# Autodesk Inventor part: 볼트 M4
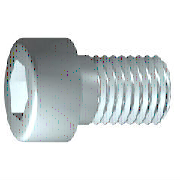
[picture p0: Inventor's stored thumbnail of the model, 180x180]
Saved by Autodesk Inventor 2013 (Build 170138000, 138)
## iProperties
IsCustomPart: 0
Created: 2014-10
Part Number: 볼트 M4
Material: 강철, 연강
Description: 6각머리 태핑 나사
Document SubType Name: Modeling
Standard: KS B 1003
Designer: KYOUNG IL JANG
Standards Organization: KS
Language: ko-KR
Size Designation: M 4 x 10
Categories: <MemberInstance><Categories><Category DisplayName="조임쇠" InternalName="e4da775c-781d-43d5-af7c-5136215cf5a6" Mnemonic="FSTN"><Category DisplayName="볼트" InternalN
Density: 7.86 g/cm^3
Mass: 2.0371 g
Surface Area: 3.0572 cm^2
Volume: 0.259174 cm^3
Author: SeoGD™ [www.esajin.kr]
Revision Number: 1
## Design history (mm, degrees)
sketch "스케치1"
  geometry: L1 (-1, 0)-(10, 0); L2 (10, 0)-(10, 2); L3 (10, 2)-(1.75, 2); L4 (1.75, 2)-(1.32, 2); L5 (1.32, 2)-(0, 2); L6 (0, 2)-(0, 3.5); L7 (0, 3.5)-(-4, 3.5); L8 (-4, 3.5)-(-4, 1.732); L9 (-4, 1.732)-(-2, 1.732); L10 (-2, 1.732)-(-1, 0); L11 (-6.8, 0)-(12.8, 0) reference; L12 (0, -0.7)-(0, 4.2) reference; L13 (1.75, 2)-(0, 2)
  constraints: 22 end point, 6 parallel, 2 collinear, 2 perpendicular, 1 horizontal, 1 point on line
  dimensions: "d1" = 8.25 distance from line of L3.end L2 (= GEL); "d2" = 0.42952 distance of L4.end L3.end (computed from GAL); "d3" = 4 distance between parallel lines of L8 L6 (= KOH); "d4" = 2 distance of L8.end L9.end (= INTI); "d5" = 60 deg angle of L10 L1; "d6" = 4 diameter of L3 L1 (= GD); "d7" = 4 diameter of L5 L1 (= BDM); "d8" = 3.4641 diameter of L9 L1 (= 1.1547 x SW); "d9" = 7 diameter of L7 L1 (= KOD); "d26" = 10 distance between parallel lines of L12 L2 (= NLG)
revolve "본체" sketch "스케치1" stored, may be unused: angle "d10" = 90 deg
sketch "스케치2"
  geometry: L1 (0, -4.9)-(0, 4.9) reference; L2 (-4.9, 0)-(4.9, 0) reference; L3 (1.732, 0)-(0.866, -1.5); L4 (0.866, -1.5)-(-0.866, -1.5); L5 (-0.866, -1.5)-(-1.732, 0); L6 (-1.732, 0)-(-0.866, 1.5); L7 (-0.866, 1.5)-(0.866, 1.5); L8 (0.866, 1.5)-(1.732, 0); 2 further points
  constraints: 12 end point, 1 coincident, 1 horizontal alignment, 1 point on line, 12 other
extrude "슬롯" join sketch "스케치2" stored distance "d11" = 10; taper "d12" = 0 deg
workplane "Work Plane1"
fillet "Fillet2" dims "d30" = 0.1 (= R)
body "Solid1"
fillet "모깎기1" dims "d17" = 0.4 (= RR)
feature "스레드" dims "d13" = 8.25 (= GEL), "d14" = 0
chamfer "모따기1" distance "d15" = 0.42941 (= -0.5 x SPD + 0.5 x GD); stored, may be unused: second distance "d16" = 0.42941 (= GUL), angle "d27" = 45 deg
other parameters: "GD" = 4 (= NND) [user parameter; used in 2 equation terms], "NLG" = 10 [user parameter; used in 1 equation term], "GEL" = 8.25 [user parameter; used in 2 equation terms], "KOD" = 7 [user parameter; used in 1 equation term], "KOH" = 4 [user parameter; used in 1 equation term], "INTI" = 2 [user parameter; used in 1 equation term], "GAL" = 0.42941 (= 0.61345 x PTC) [user parameter; used in 1 equation term], "GUL" = 0.42941 (= 0.61345 x PTC) [user parameter; used in 1 equation term], "BDM" = 4 (= NND) [user parameter; used in 1 equation term], "SW" = 3 [user parameter; used in 2 equation terms], "RR" = 0.4 [user parameter; used in 1 equation term], "SPD" = 3.14117 (= NND - 1.2269 x PTC) [user parameter; used in 1 equation term], "d19" = 0, "d28" = 0, "d29" = 0, "R" = 0.1 [user parameter; used in 1 equation term], "PHH" = 0.2 [user parameter], "GD1" = 3.14117 (= THREADDIA - 1.2269 x PTC) [user parameter], "THREADDIA" = 4 [user parameter; used in 1 equation term], "FAWI" = 45 deg [user parameter], "TPU" = 14.28571 (computed from PTC) [user parameter], "PTC" = 0.7 [user parameter; used in 5 equation terms], "NND" = 4 [user parameter; used in 3 equation terms], "TOA" = 30 deg [user parameter], "E0" = 3.465 (= 1.155 x SW) [user parameter]
